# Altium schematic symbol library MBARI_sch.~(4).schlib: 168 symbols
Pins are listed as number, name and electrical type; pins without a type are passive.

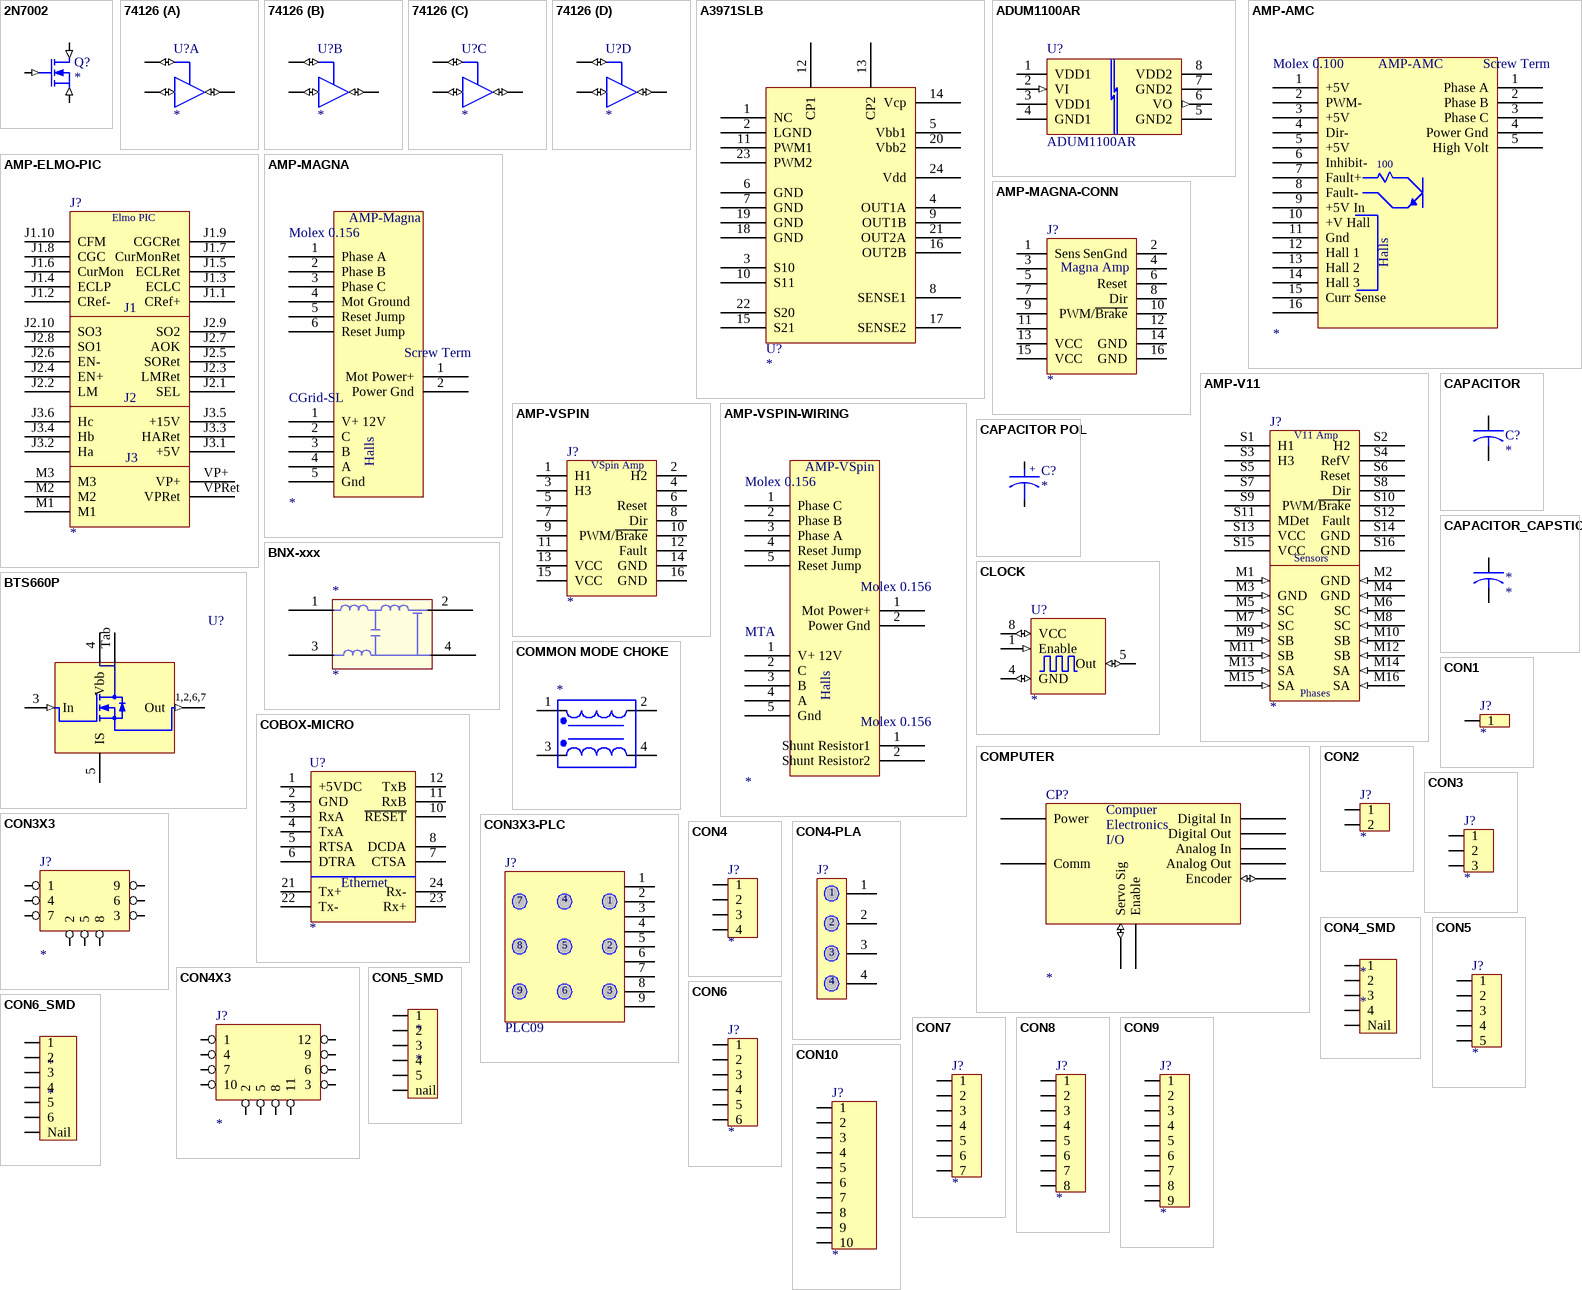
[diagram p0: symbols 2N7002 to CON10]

## 2N7002
designator Q?
N-Channel FET
footprint SOT-23
pins: 1 G (in), 2 S (in), 3 D (in)

## 74126
designator U?
Tri-State Quad Buffer
footprint DIP14
pins on every part: 7 GND (io) hidden to GND, 14 VCC (io) hidden to VCC
part A pins: 1 C1 (io), 2 A1 (io), 3 Y1 (io)
part B pins: 4 C2 (io), 5 A2 (io), 6 Y2 (io)
part C pins: 8 Y3 (io), 9 A3 (io), 10 C3 (io)
part D pins: 11 Y4 (io), 12 A4 (io), 13 C4 (io)

## A3971SLB
designator U?
Allegro Dual DMOS Full-Bridge Driver
footprint Allegro SOIC 24
pins: 1 NC, 2 LGND, 3 S10, 4 OUT1A, 5 Vbb1, 6 GND, 7 GND, 8 SENSE1, 9 OUT1B, 10 S11, 11 PWM1, 12 CP1, 13 CP2, 14 Vcp, 15 S21, 16 OUT2B, 17 SENSE2, 18 GND, 19 GND, 20 Vbb2, 21 OUT2A, 22 S20, 23 PWM2, 24 Vdd

## ADUM1100AR
designator U?
Digital Isolator; Manufacturer: Analog Devices; Vendor: Arrow Electronics
footprint SO-G8/D5
pins: 1 VDD1 (power), 2 VI (in), 3 VDD1 (power), 4 GND1 (power), 5 GND2 (power), 6 VO (out), 7 GND2 (power), 8 VDD2 (power)

## AMP-AMC
designator ?
pins: 1 Phase A (power), 1 +5V (power), 2 Phase B (power), 2 PWM- (power), 3 Phase C (power), 3 +5V (power), 4 Power Gnd (power), 4 Dir- (power), 5 High Volt (power), 5 +5V (power), 6 Inhibit- (power), 7 Fault+ (power), 8 Fault- (power), 9 +5V In (power), 10 +V Hall (power), 11 Gnd (power), 12 Hall 1 (power), 13 Hall 2 (power), 14 Hall 3 (power), 15 Curr Sense (power), 16 (power)

## AMP-ELMO-PIC
designator J?
Elmo Piccolo Amp
footprint ELMO-PIC
pins: J1.1 CRef+, J1.2 CRef-, J1.3 ECLC, J1.4 ECLP, J1.5 ECLRet, J1.6 CurMon, J1.7 CurMonRet, J1.8 CGC, J1.9 CGCRet, J1.10 CFM, J2.1 SEL, J2.2 LM, J2.3 LMRet, J2.4 EN+, J2.5 SORet, J2.6 EN-, J2.7 AOK, J2.8 SO1, J2.9 SO2, J2.10 SO3, J3.1 +5V, J3.2 Ha, J3.3 HARet, J3.4 Hb, J3.5 +15V, J3.6 Hc, M1, M2, M3, VP+, VPRet

## AMP-MAGNA
designator ?
pins: 1 Phase A (power), 1 V+ 12V (power), 1 Mot Power+ (power), 2 Phase B (power), 2 C (power), 2 Power Gnd (power), 3 Phase C (power), 3 B (power), 4 Mot Ground (power), 4 A (power), 5 Gnd (power), 5 Reset Jump (power), 6 Reset Jump (power)

## AMP-MAGNA-CONN
designator J?
Magma Amp board 2x8, 2mm connector
footprint HDR2X8_2MM
pins: 1 Sens (power), 2 SenGnd (power), 3 (power), 4 (power), 5 (power), 6 Reset (power), 7 (power), 8 Dir (power), 9 (power), 10 PWM/~{Brake} (power), 11 (power), 12 (power), 13 VCC (power), 14 GND (power), 15 VCC (power), 16 GND (power)

## AMP-V11
designator J?
Velocity11 Amp board 2 2x8, 2mm connectors
footprint V11-AMP
pins: M1 (in), M2 GND (in), M3 GND (in), M4 GND (in), M5 SC (in), M6 SC (in), M7 SC (in), M8 SC (in), M9 SB (in), M10 SB (in), M11 SB (in), M12 SB (in), M13 SA (in), M14 SA (in), M15 SA (in), M16 SA (in), S1 H1 (power), S2 H2 (power), S3 H3 (power), S4 RefV (power), S5 (power), S6 Reset (power), S7 (power), S8 Dir (power), S9 (power), S10 PWM/~{Brake} (power), S11 MDet (power), S12 Fault (power), S13 VCC (power), S14 GND (power), S15 VCC (power), S16 GND (power)

## AMP-VSPIN
designator J?
VSpin Amp board 2x8, 2mm connector
footprint VSPIN-AMP
pins: 1 H1 (power), 2 H2 (power), 3 H3 (power), 4 (power), 5 (power), 6 Reset (power), 7 (power), 8 Dir (power), 9 (power), 10 PWM/~{Brake} (power), 11 (power), 12 Fault (power), 13 VCC (power), 14 GND (power), 15 VCC (power), 16 GND (power)

## AMP-VSPIN-WIRING
designator ?
pins: 1 Phase C (power), 1 V+ 12V (power), 1 Mot Power+ (power), 1 Shunt Resistor1, 2 Phase B (power), 2 C (power), 2 Power Gnd (power), 2 Shunt Resistor2, 3 Phase A (power), 3 B (power), 4 A (power), 4 Reset Jump (power), 5 Gnd (power), 5 Reset Jump (power)

## BNX-xxx
designator *
pins: 1 B, 2 CB, 3 PSG, 4 CG

## BTS660P
designator U?
High Side High Current ProFET; ManufPartNo: BTS660P; Manufacturer: Infineon
footprint TO-220-7-3 (Footprint not found)
footprint TO-220-7SMD (Footprint not found)
pins: 1 Out (out), 2 Out (out), 3 In (in) "Ground to turn on", 4 Vbb (power), 5 IS "Current sense", 6 Out (out), 7 Out (out), Tab Vbb (power)

## CAPACITOR
designator C?
Capacitor
pins: 1, 2

## CAPACITOR POL
designator C?
Capacitor
pins: 1, 2

## CAPACITOR_CAPSTICK
designator *
pins: 1, 2

## CLOCK
designator U?
Clock Chip
footprint DIP8
pins: 1 Enable (in), 4 GND (io), 5 Out (io), 8 VCC (io)

## COBOX-MICRO
designator U?
CoBox Micro Terminal Server
footprint COBOX-MICRO
pins: 1 +5VDC, 2 GND, 3 RxA, 4 TxA, 5 RTSA, 6 DTRA, 7 CTSA, 8 DCDA, 10 ~{RESET}, 11 RxB, 12 TxB, 21 Tx+, 22 Tx-, 23 Rx+, 24 Rx-

## COMMON MODE CHOKE
designator *  (mechanical)
footprint Pulse_BigFoot (Pulse engineering big foot footprint)
pins: 1 (power), 2, 3, 4

## COMPUTER
designator CP?
computer
pins: 1 Power (power), 2 Digital In (power), 3 Digital Out (power), 4 Analog In (power), 5 Analog Out (power), 6 Comm (power), 7 Enable (power), 8 Servo Sig (io), 15 Encoder (io)

## CON1
designator J?
Connector
footprint SIP1
pins: 1

## CON2
designator J?
Connector
footprint SIP2
pins: 1, 2

## CON3
designator J?
Connector
footprint SIP3
pins: 1, 2, 3

## CON3X3
designator J?
9 pin connector
footprint PHOENIX1803497
footprint SIP9
footprint CGRID9
footprint MTA-9
pins: 1 (io), 2 (io), 3 (io), 4 (io), 5 (io), 6 (io), 7 (io), 8 (io), 9 (io)

## CON3X3-PLC
designator J?, comment PLC09
Positronic 9 pin connector
footprint PLC09 (Positronic 3x3 pins)
footprint PLC09-RA
pins: 1 (power), 2 (power), 3 (power), 4 (power), 5 (power), 6 (power), 7 (power), 8 (power), 9 (power)

## CON4
designator J?
Connector
footprint SIP4
footprint Microfit3-1x4 SMT RA Nail (Microfit 3 Single Row 4 Position SMT Right Angle Nail)
pins: 1, 2, 3, 4

## CON4-PLA
designator J?
Positronic 4 pin connector; ManufPartNo: PLA04
footprint PLA04 (Positronic 1x4 pin)
footprint PLA04-RA
pins: 1, 2, 3, 4

## CON4_SMD
designator *
footprint Microfit3-1x4 SMT RA Nail (Microfit 3 Single Row 4 Position SMT Right Angle Nail)
pins: 1, 2, 3, 4, nail Nail

## CON4X3
designator J?
12 pin connector
footprint PHOENIX1803523
footprint SIP12
footprint CGRID12
pins: 1 (io), 2 (io), 3 (io), 4 (io), 5 (io), 6 (io), 7 (io), 8 (io), 9 (io), 10 (io), 11 (io), 12 (io)

## CON5
designator J?
Connector
footprint SIP5
pins: 1, 2, 3, 4, 5

## CON5_SMD
designator *
Connector
footprint Microfit3-1x5 SMT RA Nail (Microfit 3.0 Single Row SMT with Nails 5 Position)
pins: 1, 2, 3, 4, 5, nail

## CON6
designator J?
Connector
footprint SIP6
pins: 1, 2, 3, 4, 5, 6

## CON6_SMD
designator *
footprint Microfit3-1x6 SMT RA Nail (Microfit 3 Single Row 6 Position SMT Right Angle Nail)
pins: 1, 2, 3, 4, 5, 6, Nail "mechanical"

## CON7
designator J?
Connector
footprint SIP7
pins: 1, 2, 3, 4, 5, 6, 7

## CON8
designator J?
Connector
footprint SIP8
pins: 1, 2, 3, 4, 5, 6, 7, 8

## CON9
designator J?
Connector
footprint SIP9
pins: 1, 2, 3, 4, 5, 6, 7, 8, 9

## CON10
designator J?
Connector
footprint SIP10
pins: 1, 2, 3, 4, 5, 6, 7, 8, 9, 10

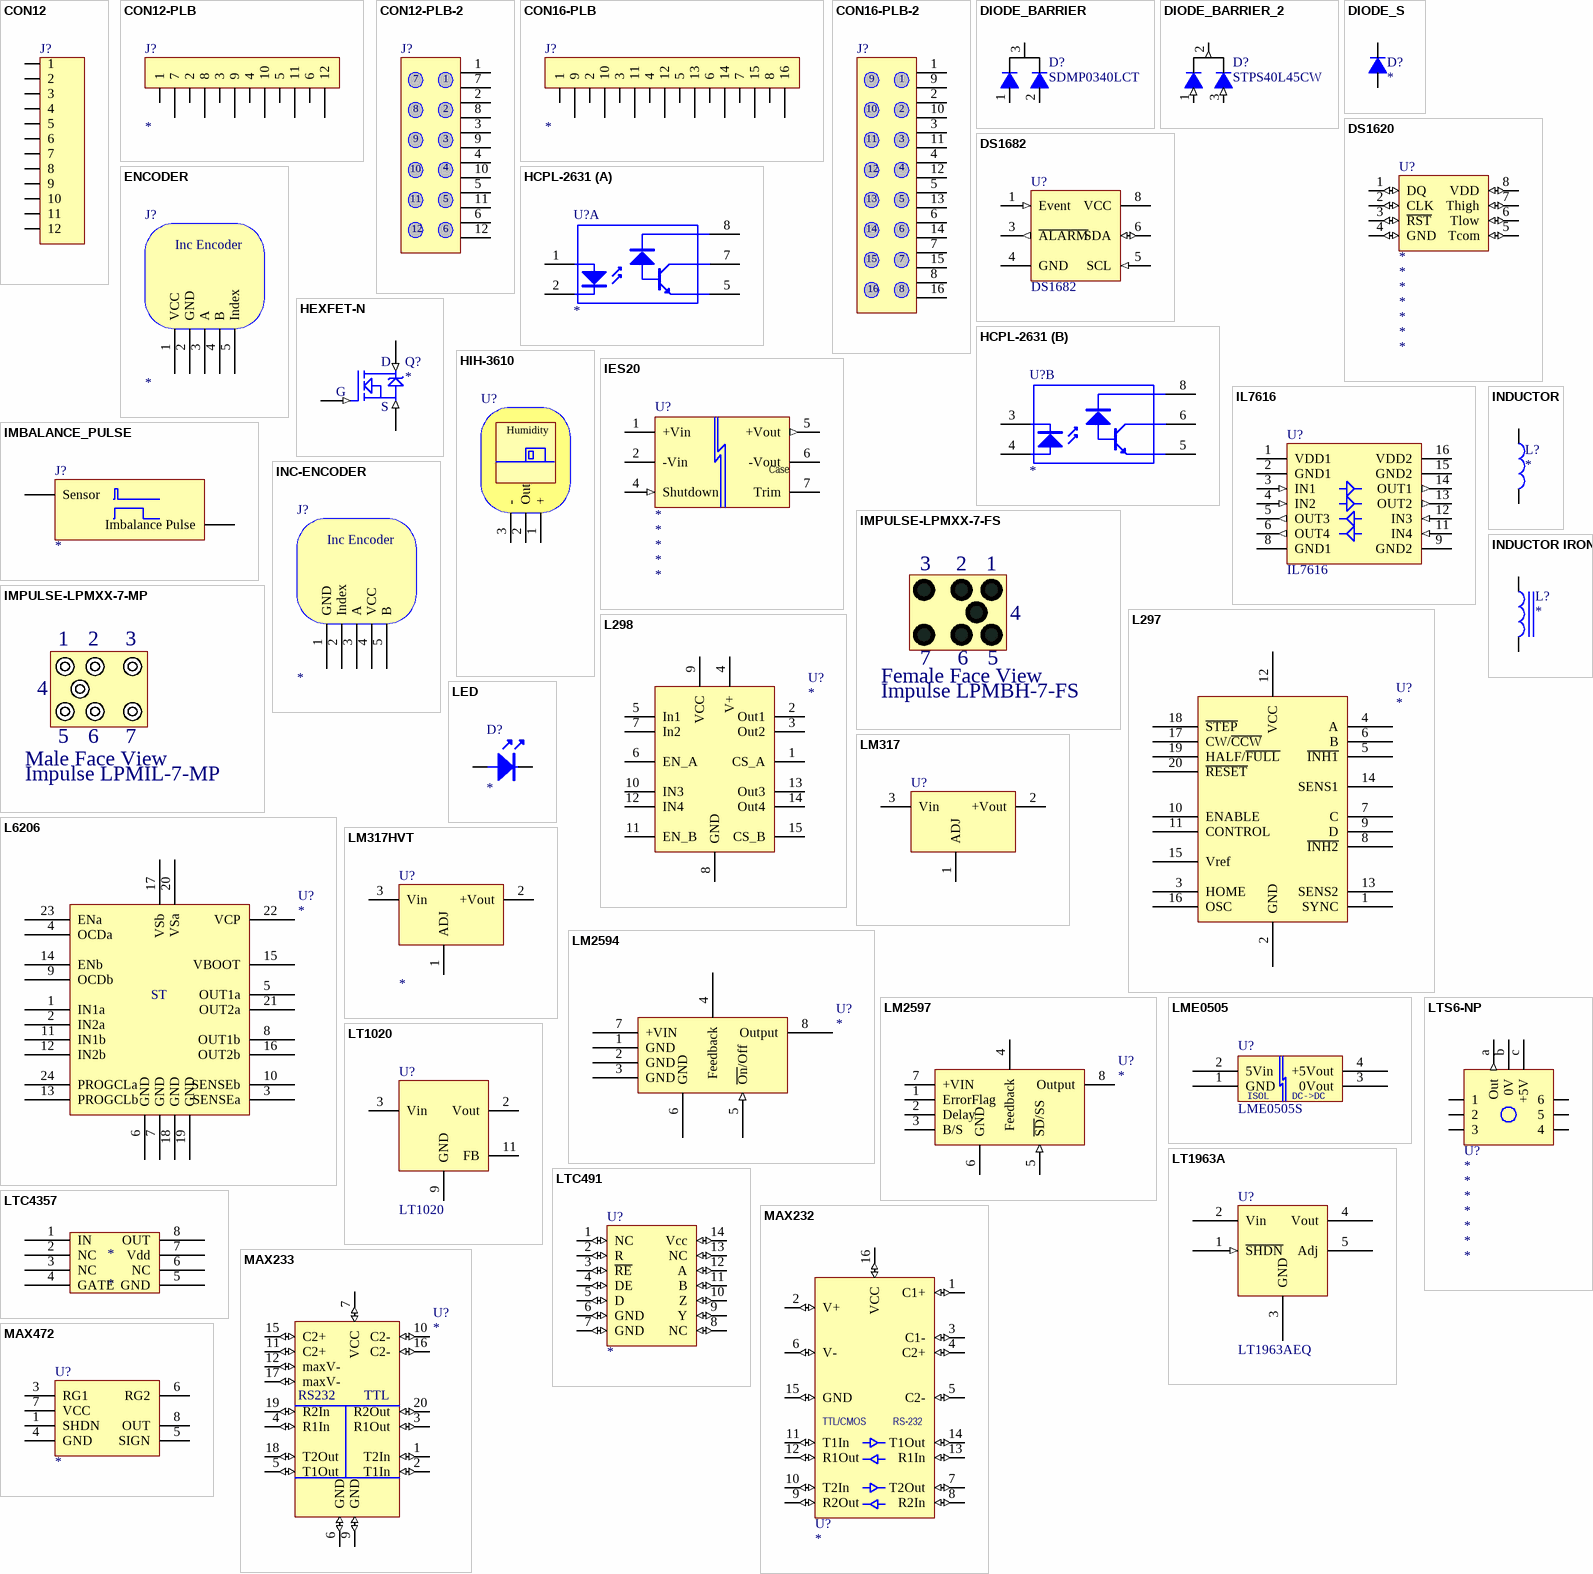
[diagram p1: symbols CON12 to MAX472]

## CON12
designator J?
Connector 12 pin
footprint SIP12 (Footprint not found)
pins: 1, 2, 3, 4, 5, 6, 7, 8, 9, 10, 11, 12

## CON12-PLB
designator J?
Positronic 12 pin connector
footprint PLB12
footprint PLB12-RA
pins: 1, 2, 3, 4, 5, 6, 7, 8, 9, 10, 11, 12

## CON12-PLB-2
designator J?
Positronic 12 pin connector; ManufPartNo: PLB12
footprint PLB12
footprint PLB12-RA
pins: 1, 2, 3, 4, 5, 6, 7, 8, 9, 10, 11, 12

## CON16-PLB
designator J?
Positronic 16 pin connector
footprint PLB16
footprint PLB16-RA
pins: 1, 2, 3, 4, 5, 6, 7, 8, 9, 10, 11, 12, 13, 14, 15, 16

## CON16-PLB-2
designator J?
Positronic 16 pin connector; ManufPartNo: PLB16
footprint PLB16 (Positronic 2x8 pins)
footprint PLB16-RA
pins: 1, 2, 3, 4, 5, 6, 7, 8, 9, 10, 11, 12, 13, 14, 15, 16

## DIODE_BARRIER
designator D?, comment SDMP0340LCT
Schottky Barrier Diode, Com Cathode; Manufacturer: Diodes Inc; VendorPartNo: SDMP0340LCTDICT-ND; Cost/ea: .065; Reference: T033, 581; Vendor: Digi-Key
footprint SOT-523 (Diodes Inc SOT-523)
pins: 1 A1 (io), 2 A2 (io), 3 K (io)

## DIODE_BARRIER_2
designator D?, comment STPS40L45CW
Schottky Barrier Diode, Com Cathode; Manufacturer: IRF
footprint TO-247AC (Footprint not found)
pins: 1 A1 (in), 2 K (out), 3 A2 (in)

## DIODE_S
designator D?
Diode
footprint DIODE0.4
pins: 1 K (io), 2 A (io)

## DS1620
designator U?
DallasSemi Digital Thermometer and Thermostat
footprint DIP-8
footprint SO-8
pins: 1 DQ (io), 2 CLK (io), 3 ~{RST} (io), 4 GND (io), 5 Tcom (io), 6 Tlow (io), 7 Thigh (io), 8 VDD (io)

## DS1682
designator U?
Dallas Semi Elapsed Time Recorder with Alarm
footprint SOIC-8
pins: 1 Event (in) "Active High", 3 ~{ALARM} (out), 4 GND (power), 5 SCL (in) "Serial Clock", 6 SDA (io) "Serial I/O", 8 VCC (power) "2.5 - 5.5 VDC"

## ENCODER
designator J?
encoder
pins: 1 VCC (power), 2 GND (power), 3 A (power), 4 B (power), 5 Index (power)

## HCPL-2631
designator U?
Optoisolator
footprint DIP8
pins on every part: 5 GND, 8 VCC (power)
part A pins: 1 A1, 2 K2, 7 Vo1
part B pins: 3 A2, 4 K2, 6 Vo2

## HEXFET-N
designator Q?
HexFET
footprint HEXFET-DIP4
pins: 1 G (in), 2 D (in), 3 S (in)

## HIH-3610
designator U?
Humidity Sensor
footprint SIP3
footprint SIP3_050
footprint HIH3610_100
footprint HIH3610_050
pins: 1 + (power), 2 Out (power), 3 - (power)

## IES20
designator U?
Power One IES 20W DC->DC Isolated Converter
footprint POWERONE-IES
pins: 1 +Vin (power), 2 -Vin (power), 4 Shutdown (in), 5 +Vout (out), 6 -Vout (power), 7 Trim

## IL7616
designator U?
NVE IsoLoop Digital Coupler; Cost/ea: 7.10; Vendor: Digi-Key
footprint SOIC16-0.15 (Footprint not found)
footprint SOIC16-0.3 (Footprint not found)
pins: 1 VDD1 (power), 2 GND1 (power), 3 IN1 (in), 4 IN2 (in), 5 OUT3 (out), 6 OUT4 (out), 8 GND1 (power), 9 GND2 (power), 11 IN4 (in), 12 IN3 (in), 13 OUT2 (out), 14 OUT1 (out), 15 GND2 (power), 16 VDD2 (power)

## IMBALANCE_PULSE
designator J?
safety circuit
pins: 2 Sensor (power), 3 Imbalance Pulse (power)

## IMPULSE-LPMXX-7-FS
designator J?  DescSheet: Impulse LPMBH-7-FS
Impulse LPMxx-7-FS Connector; DescSheet: Impulse LPMIL-7-FS

## IMPULSE-LPMXX-7-MP
designator J?  DescSheet: Impulse LPMIL-7-MP
Impulse LPMxx-7-MP Connector; DescSheet: Impulse LPMBH-7-MP

## INC-ENCODER
designator J?
encoder
pins: 1 GND (power), 2 Index (power), 3 A (power), 4 VCC (power), 5 B (power)

## INDUCTOR
designator L?
Inductor
pins: 1, 2

## INDUCTOR IRON
designator L?
Inductor
pins: 1, 2

## L297
designator U?
L297 Stepper Controller
footprint DIP20
pins: 1 SYNC, 2 GND, 3 HOME, 4 A, 5 ~{INH1}, 6 B, 7 C, 8 ~{INH2}, 9 D, 10 ENABLE, 11 CONTROL, 12 VCC, 13 SENS2, 14 SENS1, 15 Vref, 16 OSC, 17 CW/~{CCW}, 18 ~{STEP}, 19 HALF/~{FULL}, 20 ~{RESET}

## L298
designator U?
Dual Full Bridge Driver
footprint MULTIWATT15V
pins: 1 CS_A, 2 Out1, 3 Out2, 4 V+, 5 In1, 6 EN_A, 7 In2, 8 GND, 9 VCC, 10 IN3, 11 EN_B, 12 IN4, 13 Out3, 14 Out4, 15 CS_B

## L6206
designator U?
DMOS Dual Full Bridge Driver
footprint DIP24
footprint SO24
pins: 1 IN1a, 2 IN2a, 3 SENSEa, 4 OCDa, 5 OUT1a, 6 GND, 7 GND, 8 OUT1b, 9 OCDb, 10 SENSEb, 11 IN1b, 12 IN2b, 13 PROGCLb, 14 ENb, 15 VBOOT, 16 OUT2b, 17 VSb, 18 GND, 19 GND, 20 VSa, 21 OUT2a, 22 VCP, 23 ENa, 24 PROGCLa

## LED
designator D?
LED
footprint LED265
pins: 1 A, 2 K

## LM317
designator U?
Regulator
footprint TO-220; pin to pad 4>2
footprint SOT-223 (4 lead SMD NS:MP04A)
pins: 1 ADJ, 2 +Vout, 3 Vin, 4 +Vout

## LM317HVT
designator U?
Regulator
footprint TO-220
pins: 1 ADJ, 2 +Vout, 3 Vin

## LM2594
designator U?
Simple Switcher
footprint DIP8
pins: 1 GND, 2 GND, 3 GND, 4 Feedback, 5 ~{On}/Off (in), 6 GND (power), 7 +VIN (power), 8 Output (power)

## LM2597
designator U?
Simple Switcher 150kHz 0.5A
footprint DIP8
footprint SOIC-8
pins: 1 ErrorFlag, 2 Delay, 3 B/S, 4 Feedback, 5 ~{SD}/SS (in), 6 GND (power), 7 +VIN (power), 8 Output (power)

## LME0505
designator U?, comment LME0505S
DC->DC Isol Converter 5->5VDC; Manufacturer: C&D Technologies; VendorPartNo: 580-LME0505S; Cost/ea: 9.65; Reference: pg.741, 613; Vendor: Mouser
footprint LMEDCDC (Footprint not found)
footprint SIP4
pins: 1 GND, 2 5Vin, 3 0Vout, 4 +5Vout

## LT1020
designator U?
Micropower Regulator; Manufacturer: Linear Technology; Vendor: Digi-Key
footprint DIP14
footprint SOIC-16-0.3W (LTC SW pkg DWG# 05-08-1620); pin to pad 9>11 11>13
pins: 2 Vout (power), 3 Vin (power), 9 GND (power), 11 FB

## LT1963A
designator U?, comment LT1963AEQ
LDO Regulator, DD pkg; Manufacturer: Linear Technology; VendorPartNo: LT1963AEQ-ND; Cost/ea: 5.25; Vendor: Digi-Key
footprint DD-5 (Footprint not found)
pins: 1 ~{SHDN} (in) "~Shutdown", 2 Vin (power) "Input", 3 GND (power) "Ground", 4 Vout (power) "Output", 5 Adj "Adjust"

## LTC491
designator U?
LTC491 RS-232 <--> RS-485 converter
footprint DIP14
pins: 1 NC (io), 2 R (io), 3 ~{RE} (io), 4 DE (io), 5 D (io), 6 GND (io), 7 GND (io), 8 NC (io), 9 Y (io), 10 Z (io), 11 B (io), 12 A (io), 13 NC (io), 14 Vcc (io)

## LTC4357
designator *
pins: 1 IN, 2 NC, 3 NC, 4 GATE, 5 GND, 6 NC, 7 Vdd, 8 OUT

## LTS6-NP
designator U?
Current Transducer
footprint LTS6-NP
pins: 1, 2, 3, 4, 5, 6, a Out (out), b 0V (power), c +5V (power)

## MAX232
designator U?
MAX232 Communications Chip
footprint DIP16
pins: 1 C1+ (io), 2 V+ (io), 3 C1- (io), 4 C2+ (io), 5 C2- (io), 6 V- (io), 7 T2Out (io), 8 R2In (io), 9 R2Out (io), 10 T2In (io), 11 T1In (io), 12 R1Out (io), 13 R1In (io), 14 T1Out (io), 15 GND (io), 16 VCC (io)

## MAX233
designator U?
MAX233 Communications Chip
footprint DIP20
pins: 1 T2In (io), 2 T1In (io), 3 R1Out (io), 4 R1In (io), 5 T1Out (io), 6 GND (io), 7 VCC (io), 9 GND (io), 10 C2- (io), 11 C2+ (io), 12 maxV- (io), 15 C2+ (io), 16 C2- (io), 17 maxV- (io), 18 T2Out (io), 19 R2In (io), 20 R2Out (io)

## MAX472
designator U?
Maxim High-Side Current Monitor
footprint DIP8
footprint SO-G8/E2.5
pins: 1 SHDN, 3 RG1, 4 GND, 5 SIGN, 6 RG2, 7 VCC, 8 OUT

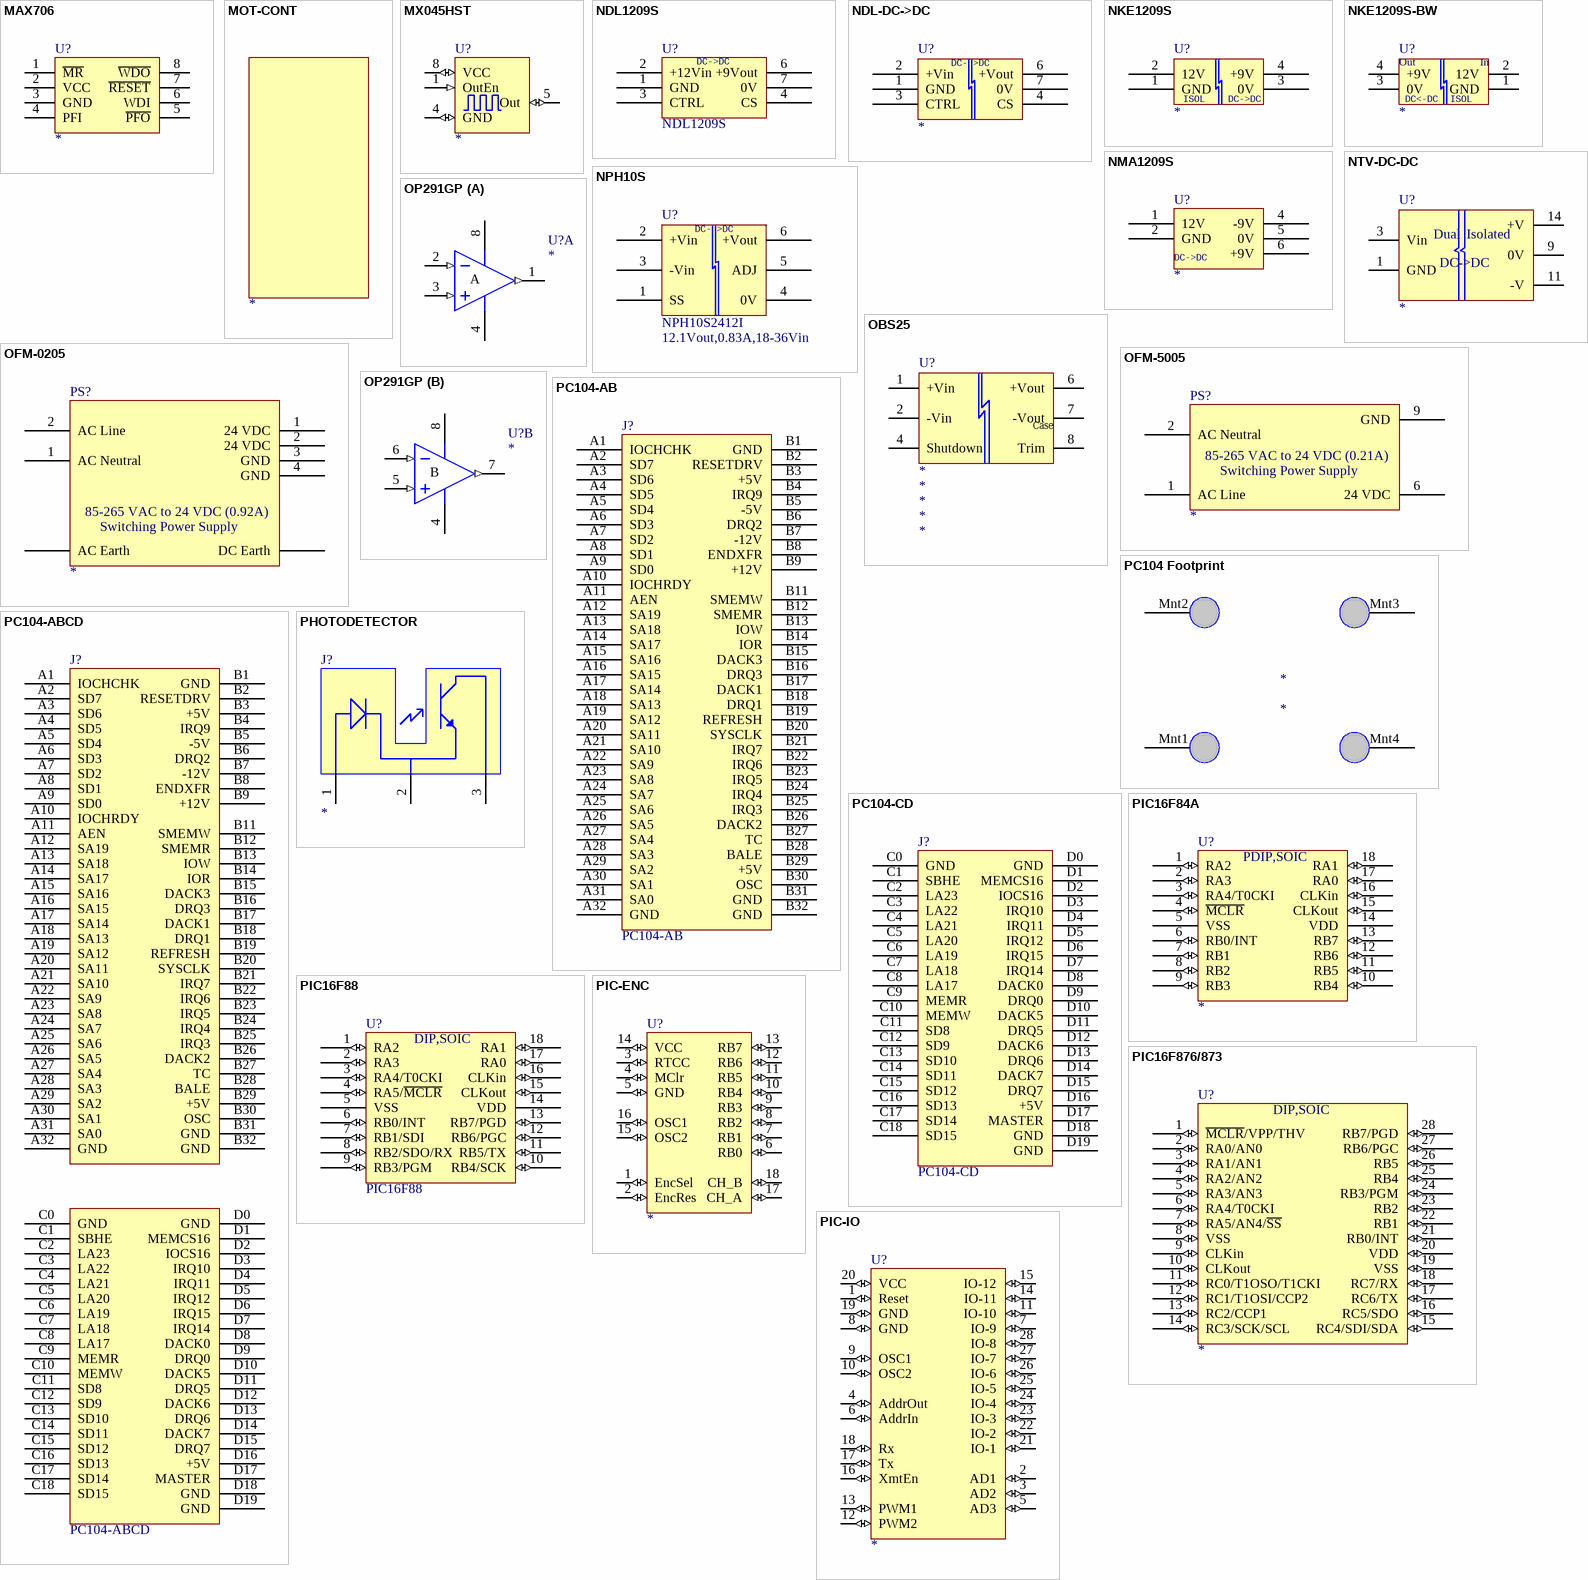
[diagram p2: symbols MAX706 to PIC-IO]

## MAX706
designator U?
Maxim uProc Supervisor
footprint DIP8
footprint SO-G8/E2.5
pins: 1 ~{MR}, 2 VCC, 3 GND, 4 PFI, 5 ~{PFO}, 6 WDI, 7 ~{RESET}, 8 ~{WDO}

## MOT-CONT
designator ?

## MX045HST
designator U?
Clock Chip
footprint DIP8
pins: 1 OutEn (in), 4 GND (io), 5 Out (io), 8 VCC (io)

## NDL1209S
designator U?
DC->DC Isol Converter 12->9VDC
footprint NDLDCDC
footprint SIP8
pins: 1 GND, 2 +12Vin, 3 CTRL, 4 CS, 6 +9Vout, 7 0V

## NDL-DC->DC
designator U?
DC->DC Isol Converter
footprint NDLDCDC
footprint SIP8
pins: 1 GND, 2 +Vin, 3 CTRL, 4 CS, 6 +Vout, 7 0V

## NKE1209S
designator U?
DC->DC Isol Converter 12->9VDC
footprint NKEDCDC
footprint SIP4
pins: 1 GND, 2 12V, 3 0V, 4 +9V

## NKE1209S-BW
designator U?
DC->DC Isol Converter 12->9VDC
footprint NKEDCDC
footprint SIP4
pins: 1 GND, 2 12V, 3 0V, 4 +9V

## NMA1209S
designator U?
DC->DC Isol Converter 12->9VDC
footprint NMADCDC
footprint SIP7
pins: 1 12V, 2 GND, 4 -9V, 5 0V, 6 +9V

## NPH10S
designator U?, comment NPH10S2412I  DescSheet: 12.1Vout,0.83A,18-36Vin
DC->DC Isol Converter 10W; Manufacturer: C&D Technologies; VendorPartNo: 580-NPH10S2412I; Cost/ea: 36.18; Reference: pg.1069; Vendor: Mouser
footprint NPH10S
pins: 1 SS, 2 +Vin, 3 -Vin, 4 0V, 5 ADJ, 6 +Vout

## NTV-DC-DC
designator U?
Dual Isol DC->DC Converter
footprint SO-NTV
pins: 1 GND, 3 Vin, 9 0V, 11 -V, 14 +V

## OBS25
designator U?
Power One OBS 25W DC->DC Isolated Converter
footprint POWERONE-OBS
pins: 1 +Vin, 2 -Vin, 4 Shutdown, 6 +Vout, 7 -Vout, 8 Trim

## OFM-0205
designator PS?
Astrodyne power supply 20 watts
footprint OFM020
pins: 1 AC Neutral, 1 24 VDC, 2 AC Line, 2 24 VDC, 3 GND, 4 GND, 10 AC Earth, 11 DC Earth

## OFM-5005
designator PS?
Astrodyne power supply 20 watts
footprint OFM020
pins: 1 AC Line, 2 AC Neutral, 6 24 VDC, 9 GND

## OP291GP
designator U?
Micropower Single-Supply Rail-to-Rail Input/Output Operational Amplifier
footprint DIP8
simulation model OP291G (SUBCKT)
pins on every part: 4 V- (power), 8 V+ (power)
part A pins: 1 OUT (out), 2 IN- (in), 3 IN+ (in)
part B pins: 5 IN+ (in), 6 IN- (in), 7 OUT (out)

## PC104 Footprint
designator *
pins: Mnt1, Mnt2, Mnt3, Mnt4

## PC104-AB
designator J?
PC/104 A&B rails
footprint PC104-AB (Footprint not found)
pins: A1 IOCHCHK, A2 SD7, A3 SD6, A4 SD5, A5 SD4, A6 SD3, A7 SD2, A8 SD1, A9 SD0, A10 IOCHRDY, A11 AEN, A12 SA19, A13 SA18, A14 SA17, A15 SA16, A16 SA15, A17 SA14, A18 SA13, A19 SA12, A20 SA11, A21 SA10, A22 SA9, A23 SA8, A24 SA7, A25 SA6, A26 SA5, A27 SA4, A28 SA3, A29 SA2, A30 SA1, A31 SA0, A32 GND, B1 GND, B2 RESETDRV, B3 +5V, B4 IRQ9, B5 -5V, B6 DRQ2, B7 -12V, B8 ENDXFR, B9 +12V, B10 KEY hidden, B11 SMEMW, B12 SMEMR, B13 IOW, B14 IOR, B15 DACK3, B16 DRQ3, B17 DACK1, B18 DRQ1, B19 REFRESH, B20 SYSCLK, B21 IRQ7, B22 IRQ6, B23 IRQ5, B24 IRQ4, B25 IRQ3, B26 DACK2, B27 TC, B28 BALE, B29 +5V, B30 OSC, B31 GND, B32 GND

## PC104-ABCD
designator J?
PC104 ABCD Rails
footprint PC104-ABCD (Footprint not found)
pins: A1 IOCHCHK, A2 SD7, A3 SD6, A4 SD5, A5 SD4, A6 SD3, A7 SD2, A8 SD1, A9 SD0, A10 IOCHRDY, A11 AEN, A12 SA19, A13 SA18, A14 SA17, A15 SA16, A16 SA15, A17 SA14, A18 SA13, A19 SA12, A20 SA11, A21 SA10, A22 SA9, A23 SA8, A24 SA7, A25 SA6, A26 SA5, A27 SA4, A28 SA3, A29 SA2, A30 SA1, A31 SA0, A32 GND, B1 GND, B2 RESETDRV, B3 +5V, B4 IRQ9, B5 -5V, B6 DRQ2, B7 -12V, B8 ENDXFR, B9 +12V, B11 SMEMW, B12 SMEMR, B13 IOW, B14 IOR, B15 DACK3, B16 DRQ3, B17 DACK1, B18 DRQ1, B19 REFRESH, B20 SYSCLK, B21 IRQ7, B22 IRQ6, B23 IRQ5, B24 IRQ4, B25 IRQ3, B26 DACK2, B27 TC, B28 BALE, B29 +5V, B30 OSC, B31 GND, B32 GND, C0 GND, C1 SBHE, C2 LA23, C3 LA22, C4 LA21, C5 LA20, C6 LA19, C7 LA18, C8 LA17, C9 MEMR, C10 MEMW, C11 SD8, C12 SD9, C13 SD10, C14 SD11, C15 SD12, C16 SD13, C17 SD14, C18 SD15, D0 GND, D1 MEMCS16, D2 IOCS16, D3 IRQ10, D4 IRQ11, D5 IRQ12, D6 IRQ15, D7 IRQ14, D8 DACK0, D9 DRQ0, D10 DACK5, D11 DRQ5, D12 DACK6, D13 DRQ6, D14 DACK7, D15 DRQ7, D16 +5V, D17 MASTER, D18 GND, D19 GND

## PC104-CD
designator J?
PC/104 C&D rails
footprint PC104-CD (Footprint not found)
pins: C0 GND, C1 SBHE, C2 LA23, C3 LA22, C4 LA21, C5 LA20, C6 LA19, C7 LA18, C8 LA17, C9 MEMR, C10 MEMW, C11 SD8, C12 SD9, C13 SD10, C14 SD11, C15 SD12, C16 SD13, C17 SD14, C18 SD15, C19 KEY hidden, D0 GND, D1 MEMCS16, D2 IOCS16, D3 IRQ10, D4 IRQ11, D5 IRQ12, D6 IRQ15, D7 IRQ14, D8 DACK0, D9 DRQ0, D10 DACK5, D11 DRQ5, D12 DACK6, D13 DRQ6, D14 DACK7, D15 DRQ7, D16 +5V, D17 MASTER, D18 GND, D19 GND

## PHOTODETECTOR
designator J?
slot sensor
pins: 1 A (power), 2 G (power), 3 C (power)

## PIC16F84A
designator U?
PIC16F84A microcontroller PDIP,SOIC package
footprint DIP18
pins: 1 RA2 (io), 2 RA3 (io), 3 RA4/T0CKI (io), 4 ~{MCLR} (io), 5 VSS (power), 6 RB0/INT (io), 7 RB1 (io), 8 RB2 (io), 9 RB3 (io), 10 RB4 (io), 11 RB5 (io), 12 RB6 (io), 13 RB7 (io), 14 VDD (power), 15 CLKout (io), 16 CLKin (io), 17 RA0 (io), 18 RA1 (io)

## PIC16F88
designator U?
PIC16F88 microcontroller DIP,SOIC package; Manufacturer: Microchip; Vendor: Digi-Key
footprint DIP18
pins: 1 RA2 (io), 2 RA3 (io), 3 RA4/T0CKI (io), 4 RA5/~{MCLR} (io), 5 VSS (power), 6 RB0/INT (io), 7 RB1/SDI (io), 8 RB2/SDO/RX (io), 9 RB3/PGM (io), 10 RB4/SCK (io), 11 RB5/TX (io), 12 RB6/PGC (io), 13 RB7/PGD (io), 14 VDD (power), 15 CLKout (io), 16 CLKin (io), 17 RA0 (io), 18 RA1 (io)

## PIC16F876/873
designator U?
PIC16F876/873 microcontroller DIP,SOIC package
footprint DIP28
footprint SOIC28
pins: 1 ~{MCLR}/VPP/THV (io), 2 RA0/AN0 (io), 3 RA1/AN1 (io), 4 RA2/AN2 (io), 5 RA3/AN3 (io), 6 RA4/T0CKI (io), 7 RA5/AN4/~{SS} (io), 8 VSS (io), 9 CLKin (io), 10 CLKout (io), 11 RC0/T1OSO/T1CKI (io), 12 RC1/T1OSI/CCP2 (io), 13 RC2/CCP1 (io), 14 RC3/SCK/SCL (io), 15 RC4/SDI/SDA (io), 16 RC5/SDO (io), 17 RC6/TX (io), 18 RC7/RX (io), 19 VSS (io), 20 VDD (io), 21 RB0/INT (io), 22 RB1 (io), 23 RB2 (io), 24 RB3/PGM (io), 25 RB4 (io), 26 RB5 (io), 27 RB6/PGC (io), 28 RB7/PGD (io)

## PIC-ENC
designator U?
Pic-Encoder J R Kerr
footprint DIP16
footprint SOIC16
pins: 1 EncSel (io), 2 EncRes (io), 3 RTCC (io), 4 MClr (io), 5 GND (io), 6 RB0 (io), 7 RB1 (io), 8 RB2 (io), 9 RB3 (io), 10 RB4 (io), 11 RB5 (io), 12 RB6 (io), 13 RB7 (io), 14 VCC (io), 15 OSC2 (io), 16 OSC1 (io), 17 CH_A (io), 18 CH_B (io)

## PIC-IO
designator U?
PIC-IO multifunction I/O controller
footprint DIP28_.3
pins: 1 Reset (io), 2 AD1 (io), 3 AD2 (io), 4 AddrOut (io), 5 AD3 (io), 6 AddrIn (io), 7 IO-9 (io), 8 GND (io), 9 OSC1 (io), 10 OSC2 (io), 11 IO-10 (io), 12 PWM2 (io), 13 PWM1 (io), 14 IO-11 (io), 15 IO-12 (io), 16 XmtEn (io), 17 Tx (io), 18 Rx (io), 19 GND (io), 20 VCC (io), 21 IO-1 (io), 22 IO-2 (io), 23 IO-3 (io), 24 IO-4 (io), 25 IO-5 (io), 26 IO-6 (io), 27 IO-7 (io), 28 IO-8 (io)

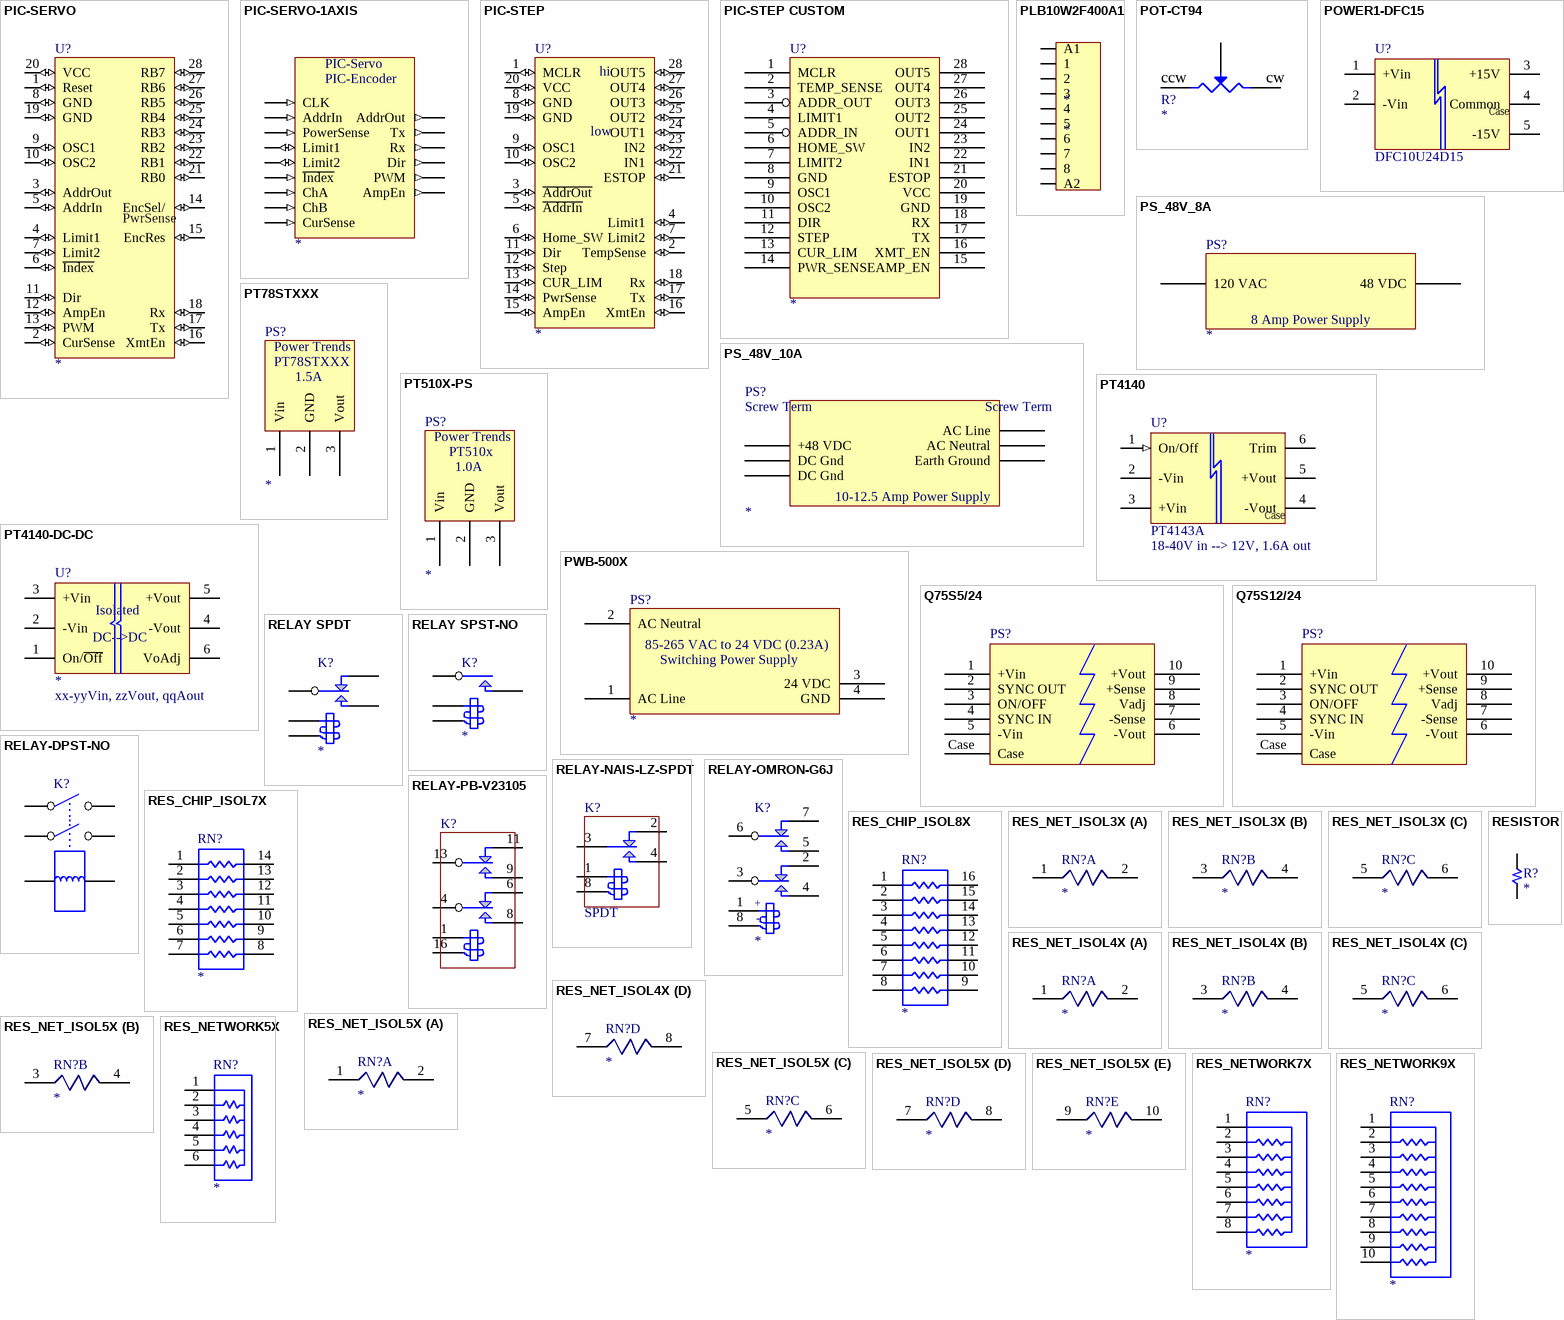
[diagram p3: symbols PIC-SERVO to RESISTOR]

## PIC-SERVO
designator U?
Pic-Servo Controller J R Kerr
footprint DIP28_.3
footprint SOIC28
pins: 1 Reset (io), 2 CurSense (io), 3 AddrOut (io), 4 Limit1 (io), 5 AddrIn (io), 6 ~{Index} (io), 7 Limit2 (io), 8 GND (io), 9 OSC1 (io), 10 OSC2 (io), 11 Dir (io), 12 AmpEn (io), 13 PWM (io), 14 EncSel/ (io), 15 EncRes (io), 16 XmtEn (io), 17 Tx (io), 18 Rx (io), 19 GND (io), 20 VCC (io), 21 RB0 (io), 22 RB1 (io), 23 RB2 (io), 24 RB3 (io), 25 RB4 (io), 26 RB5 (io), 27 RB6 (io), 28 RB7 (io)

## PIC-SERVO-1AXIS
designator ?
PIC-Servo Block with PIC-Encoder
pins: 1 CLK (in), 2 AddrIn (in), 3 PowerSense (in), 4 Limit1 (io), 5 Limit2 (io), 6 ~{Index} (in), 7 ChA (in), 8 ChB (in), 9 CurSense (in), 10 AddrOut (out), 11 Tx (out), 12 Rx (out), 13 Dir (out), 14 PWM (out), 15 AmpEn (out)

## PIC-STEP
designator U?
Pic-Step Controller J R Kerr
footprint DIP28_.3
footprint SOIC28
pins: 1 MCLR (io), 2 TempSense (io), 3 ~{AddrOut} (io), 4 Limit1 (io), 5 ~{Ad}~{drIn} (io), 6 Home_SW (io), 7 Limit2 (io), 8 GND (io), 9 OSC1 (io), 10 OSC2 (io), 11 Dir (io), 12 Step (io), 13 CUR_LIM (io), 14 PwrSense (io), 15 AmpEn (io), 16 XmtEn (io), 17 Tx (io), 18 Rx (io), 19 GND (io), 20 VCC (io), 21 ESTOP (io), 22 IN1 (io), 23 IN2 (io), 24 OUT1 (io), 25 OUT2 (io), 26 OUT3 (io), 27 OUT4 (io), 28 OUT5 (io)

## PIC-STEP CUSTOM
designator U?
Pic-Step Controller J R Kerr
footprint DIP28_.3
pins: 1 MCLR, 2 TEMP_SENSE, 3 ADDR_OUT, 4 LIMIT1, 5 ADDR_IN, 6 HOME_SW, 7 LIMIT2, 8 GND, 9 OSC1, 10 OSC2, 11 DIR, 12 STEP, 13 CUR_LIM, 14 PWR_SENSE, 15 AMP_EN, 16 XMT_EN, 17 TX, 18 RX, 19 GND, 20 VCC, 21 ESTOP, 22 IN1, 23 IN2, 24 OUT1, 25 OUT2, 26 OUT3, 27 OUT4, 28 OUT5

## PLB10W2F400A1
designator *
pins: 1, 2, 3, 4, 5, 6, 7, 8, A1, A2

## POT-CT94
designator R?
Potentiometer
footprint CT94
pins: 1 CCW, 2 W, 3 CW

## POWER1-DFC15
designator U?, comment DFC10U24D15
Power One DFC 22W DC->DC Isolated Converter +/-15V; VendorPartNo: 179-1023-ND; Manufacturer: Power-One; Cost/ea: 71.40; Reference: 1005; Vendor: Digi-Key
footprint POWERONE-DFC (Footprint not found)
pins: 1 +Vin, 2 -Vin, 3 +15V, 4 Common, 5 -15V

## PS_48V_8A
designator PS?
Power Supply
pins: 1 120 VAC (power), 3 48 VDC (power)

## PS_48V_10A
designator PS?
Power Supply
pins: 1 AC Line (power), 1 +48 VDC (power), 2 AC Neutral (power), 2 DC Gnd (power), 3 Earth Ground (power), 3 DC Gnd (power)

## PT78STXXX
designator PS?
Power Trends Switching Reg
footprint PT78ST-HORIZ
footprint PT78ST-VERT
pins: 1 Vin (power), 2 GND (power), 3 Vout (power)

## PT510X-PS
designator PS?
Power Trends Switching Reg
footprint PT510X-HORZ
footprint PT510X-VERT
pins: 1 Vin (power), 2 GND (power), 3 Vout (power)

## PT4140
designator U?, comment PT4143A  DescSheet: 18-40V in --> 12V, 1.6A out
Power Trends 20W DC->DC Isolated Converter; Manufacturer: TI Power Trends; Vendor: Digi-Key
footprint PT4140A (Footprint not found)
pins: 1 On/Off (in), 2 -Vin (power), 3 +Vin (power), 4 -Vout (power), 5 +Vout (power), 6 Trim

## PT4140-DC-DC
designator U?  DescSheet: xx-yyVin, zzVout, qqAout
TI Isol DC->DC Converter; Manufacturer: TI Powertrends; Vendor: Digi-Key
footprint TI-EGD (Footprint not found)
pins: 1 On/~{Off}, 2 -Vin (power), 3 +Vin (power), 4 -Vout (power), 5 +Vout (power), 6 VoAdj

## PWB-500X
designator PS?
Astrodyne power supply 5W watts PWB series
footprint PWB-500X
pins: 1 AC Line, 2 AC Neutral, 3 24 VDC, 4 GND

## Q75S5/24
designator PS?
BetaDyne Q75 Series Converter 5V Out 18-36V in
footprint Q75 Quarter Brick (BetaDYne Q75 Quarter Brick w/ Cu Case)
pins: 1 +Vin, 2 SYNC OUT, 3 ON/OFF, 4 SYNC IN, 5 -Vin, 6 -Vout, 7 -Sense, 8 Vadj, 9 +Sense, 10 +Vout, Case

## Q75S12/24
designator PS?
BetaDyne Q75 Series Converter
footprint Q75 Quarter Brick (BetaDYne Q75 Quarter Brick w/ Cu Case)
pins: 1 +Vin, 2 SYNC OUT, 3 ON/OFF, 4 SYNC IN, 5 -Vin, 6 -Vout, 7 -Sense, 8 Vadj, 9 +Sense, 10 +Vout, Case

## RELAY SPDT
designator K?
Relay SPDT
pins: 1 COIL1, 2 COIL2, 3 COMMON, 4 NO, 5 NC

## RELAY SPST-NO
designator K?
Relay SPST-NO
pins: 1 COIL1, 2 COIL2, 3 COMMON, 4 NO

## RELAY-DPST-NO
designator K?
Relay DPST-NO
pins: 1, 2, 3, 4, 5, 6

## RELAY-NAIS-LZ-SPDT
designator K?, comment SPDT
Nais LZ Relay SPDT; ManufPartNo: ALZ12F24; VendorPartNo: 255-1447-ND; Cost/ea: 2.16; Reference: T033, 942; Vendor: Digi-Key
footprint NAIS-LZ (Footprint not found)
pins: 1 COIL+, 2 NC, 3 COMMON, 4 NO, 5 NO hidden, 6 COMMON hidden, 7 NC hidden, 8 COIL-

## RELAY-OMRON-G6J
designator K?
Omron G6J Relay DPDT
footprint OMRON-G6J
pins: 1 COIL+, 2 NC1, 3 COMMON1, 4 NO1, 5 NO2, 6 COMMON2, 7 NC2, 8 COIL-

## RELAY-PB-V23105
designator K?
P&B V23105 Relay DPDT; ManufPartNo: V23105A5...; VendorPartNo: PB38x-ND; Reference: T033, 946; Vendor: Digi-Key
footprint DIP16
pins: 1 COIL, 4 COMMON1, 6 NC1, 8 NO1, 9 NO2, 11 NC2, 13 COMMON2, 16 COIL

## RES_CHIP_ISOL7X
designator RN?
Resistor Chip Isolated 7x
footprint DIP14
pins: 1, 2, 3, 4, 5, 6, 7, 8, 9, 10, 11, 12, 13, 14

## RES_CHIP_ISOL8X
designator RN?
Resistor Chip Isolated 8x
footprint DIP16
pins: 1, 2, 3, 4, 5, 6, 7, 8, 9, 10, 11, 12, 13, 14, 15, 16

## RES_NET_ISOL3X
designator RN?
Resistor Network Isolated 3x
footprint SIP6
part A pins: 1, 2
part B pins: 3, 4
part C pins: 5, 6

## RES_NET_ISOL4X
designator RN?
Resistor Network Isolated 4x
footprint SIP8
part A pins: 1, 2
part B pins: 3, 4
part C pins: 5, 6
part D pins: 7, 8

## RES_NET_ISOL5X
designator RN?
Resistor Network Isolated 5x
footprint SIP10
part A pins: 1, 2
part B pins: 3, 4
part C pins: 5, 6
part D pins: 7, 8
part E pins: 9, 10

## RES_NETWORK5X
designator RN?
Resistor Network, 5x
footprint SIP6
pins: 1, 2, 3, 4, 5, 6

## RES_NETWORK7X
designator RN?
Resistor Network, 7x
footprint SIP8
pins: 1, 2, 3, 4, 5, 6, 7, 8

## RES_NETWORK9X
designator RN?
Resistor Network 9x
footprint SIP10
pins: 1, 2, 3, 4, 5, 6, 7, 8, 9, 10

## RESISTOR
designator R?
Resistor
footprint AXIAL0.7
footprint AXIAL0.6
footprint AXIAL0.8
pins: 1, 2

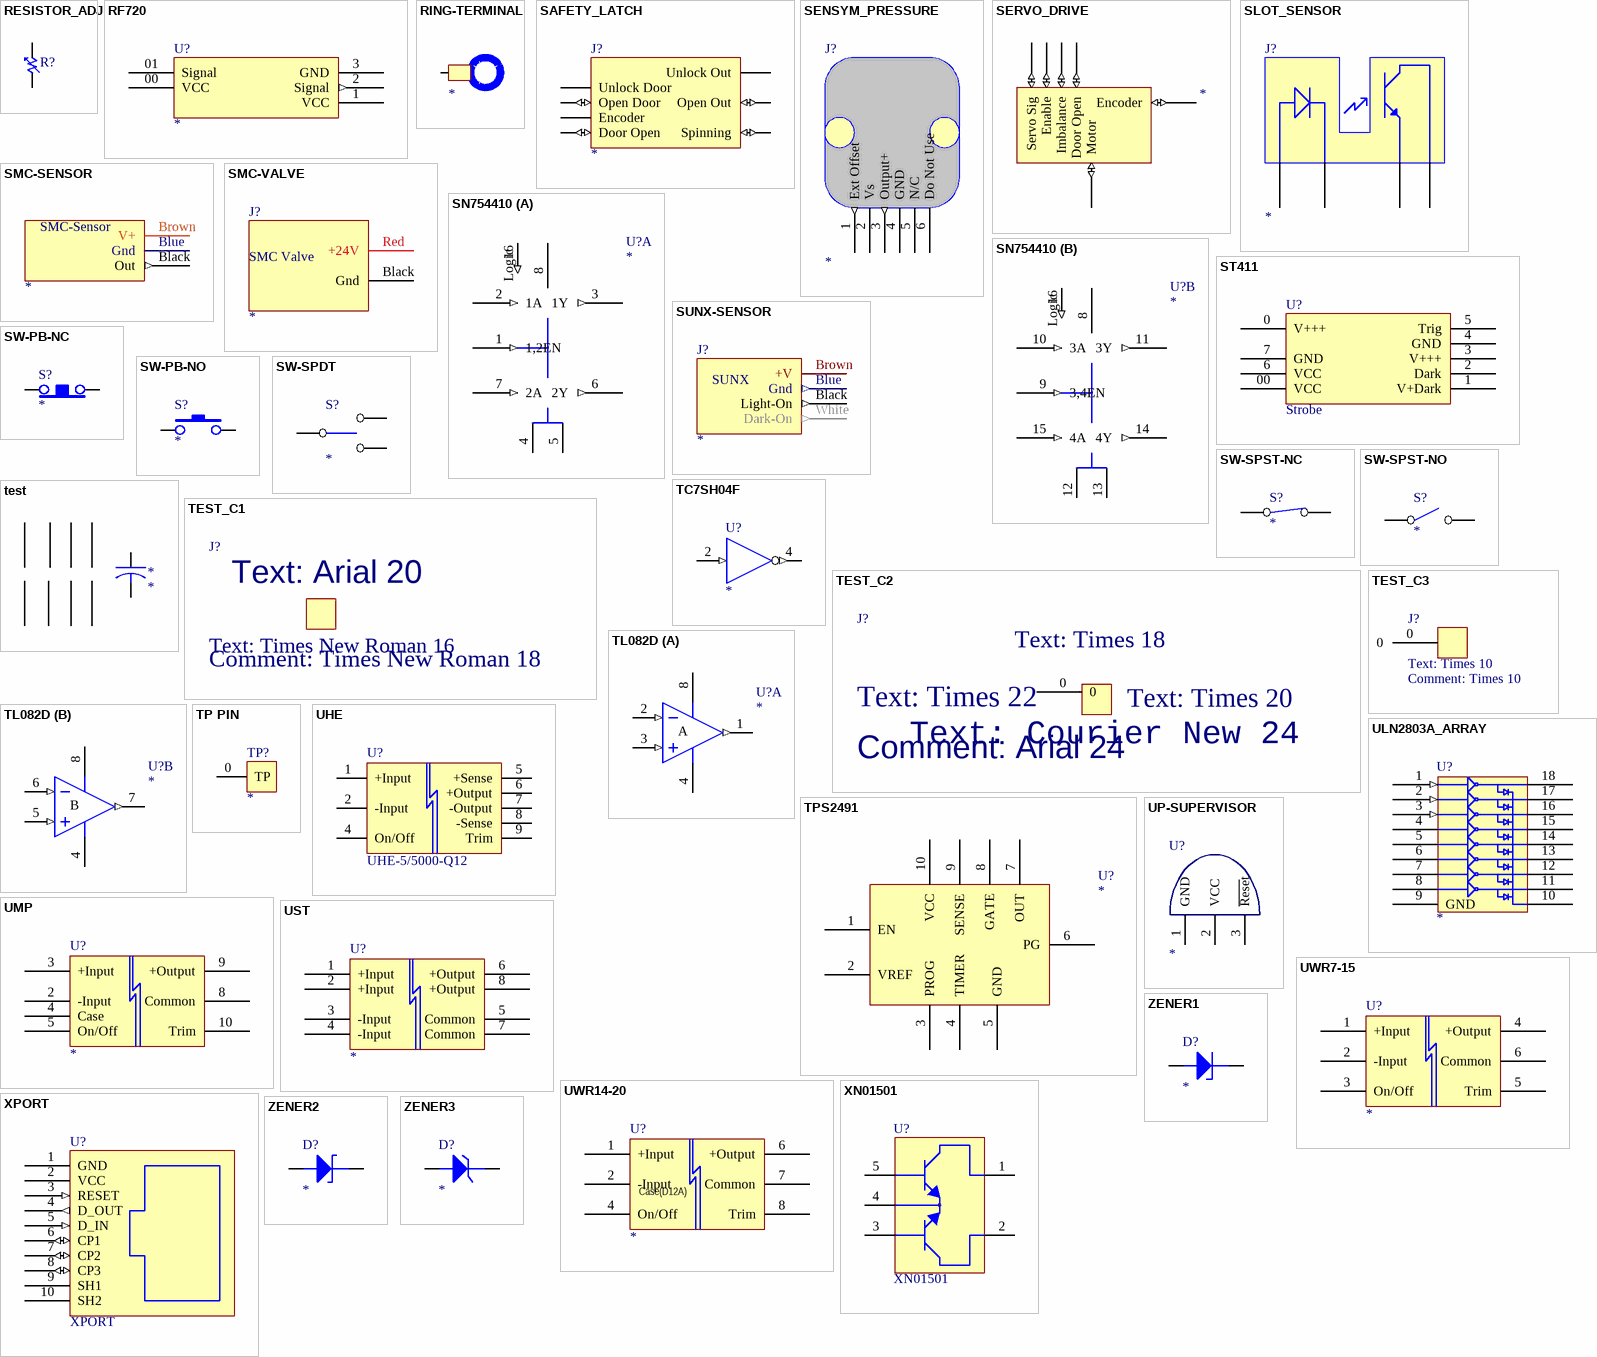
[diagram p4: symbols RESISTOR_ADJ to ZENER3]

## RESISTOR_ADJ
designator R?
Resistor Adjustable
footprint AXIAL0.7
footprint AXIAL0.6
footprint AXIAL0.8
pins: 1, 2

## RF720
designator U?
Novatech RF Beacon
footprint RF720
pins: 00 VCC (power), 1 VCC (power), 01 Signal (power), 2 Signal (out), 3 GND (power)

## RING-TERMINAL
designator ?
pins: 0

## SAFETY_LATCH
designator J?
safety circuit
pins: 1 Unlock Door (power), 2 Encoder (power), 3 Unlock Out (power), 4 Open Door (io), 5 Open Out (io), 6 Spinning (io), 7 Door Open (io)

## SENSYM_PRESSURE
designator J?
Sensym pressure sensor
footprint ASCX
pins: 1 Ext Offset (out), 2 Vs (power), 3 Output+ (out), 4 GND (power), 5 N/C, 6 Do Not Use

## SERVO_DRIVE
designator ?
pins: 9 Servo Sig (io), 10 Enable (io), 11 Motor (io), 12 Encoder (io), 13 Imbalance (io), 14 Door Open (io)

## SLOT_SENSOR
designator J?
slot sensor
pins: 1 A (power), 2 K (power), 3 C (power), 4 E (power)

## SMC-SENSOR
designator ?
pins: Black Out (out), Blue Gnd (power), Brown V+ (power)

## SMC-VALVE
designator J?
SMC Valve
pins: Black Gnd (power), Red +24V (power)

## SN754410
designator U?
Quad Half-H Driver
footprint DIP16
pins on every part: 8 VCC2 (power), 16 VCC1 (in)
part A pins: 1 1,2EN (in), 2 1A (in), 3 1Y (out), 4 GND (power), 5 GND (power), 6 2Y (out), 7 2A (in)
part B pins: 9 3,4EN (in), 10 3A (in), 11 3Y (out), 12 GND (power), 13 GND (power), 14 4Y (out), 15 4A (in)

## ST411
designator U?, comment Strobe
Novatech Strobe Beacon
footprint ST411 (Footprint not found)
pins: 00 VCC (power), 0 V+++ (power), 1 V+Dark (power), 2 Dark (power), 3 V+++ (power), 4 GND (power), 5 Trig (power), 6 VCC (power), 7 GND (power)

## SUNX-SENSOR
designator J?
SUNX slot sensor
pins: Black Light-On (out), Blue Gnd (out), Brown +V (power), White Dark-On (out)

## SW-PB-NC
designator S?
pins: 1, 2

## SW-PB-NO
designator S?
pins: 1, 2

## SW-SPDT
designator S?
pins: 1, 2, 3

## SW-SPST-NC
designator S?
pins: 1 COMMON, 2 NO

## SW-SPST-NO
designator S?
pins: 1, 2

## TC7SH04F
designator U?
Single CMOS Inverter SMD
footprint SMV-5
pins: 2 A (in), 3 GND (in) hidden to GND, 4 Y (out), 5 VCC (in) hidden to VCC

## test
designator *
pins: 1, 1, 1, 1, 1, 2, 2, 2, 2, 2

## TEST_C1
designator J?, comment Comment: Times New Roman 18

## TEST_C2
designator J?, comment Comment: Arial 24
pins: 0

## TEST_C3
designator J?, comment Comment: Times 10
pins: 0

## TL082D
designator U?
JFET-Input Operational Amplifier
footprint SO-G8/E2.5
simulation model TL082 (SUBCKT)
pins on every part: 4 V- (power), 8 V+ (power)
part A pins: 1 OUT (out), 2 IN- (in), 3 IN+ (in)
part B pins: 5 IN+ (in), 6 IN- (in), 7 OUT (out)

## TP PIN
designator TP?
Pad Pin for testpoints
footprint TP-PAD
pins: 0 TP (power)

## TPS2491
designator U?
Retry Positive High-Voltage Power-Limiting Hot Swap Controller
pins: 1 EN, 2 VREF, 3 PROG, 4 TIMER, 5 GND, 6 PG, 7 OUT, 8 GATE, 9 SENSE, 10 VCC

## UHE
designator U?, comment UHE-5/5000-Q12
Datel UHE DC->DC Isolated Converter
footprint DATEL-UHE (Datel UHE 1.6x2.0 DC/DC Converter)
pins: 1 +Input, 2 -Input, 4 On/Off, 5 +Sense, 6 +Output, 7 -Output, 8 -Sense, 9 Trim

## ULN2803A_ARRAY
designator U?
Darlington Transistor Array
footprint DIP18
pins: 1 IN (in), 2 IN (in), 3 IN (in), 4 In, 5 In, 6 In, 7 In, 8 In, 9 GND, 10 COM, 11 Out, 12 Out, 13 Out, 14 Out, 15 Out, 16 Out, 17 Out, 18 Out

## UMP
designator U?
Datel UMP DC->DC Isolated Converter
footprint DATEL_UMP
pins: 2 -Input, 3 +Input, 4 Case, 5 On/Off, 8 Common, 9 +Output, 10 Trim

## UP-SUPERVISOR
designator U?
MicroProcessor Supervisor
footprint TO92C
pins: 1 GND (power), 2 VCC (power), 3 ~{Rese}t (power)

## UST
designator U?
Datel UST DC->DC Isolated Converter
footprint DATEL_UST
pins: 1 +Input, 2 +Input, 3 -Input, 4 -Input, 5 Common, 6 +Output, 7 Common, 8 +Output

## UWR7-15
designator U?
Datel UWR DC->DC Isolated Converter
footprint DATEL_UWR
pins: 1 +Input, 2 -Input, 3 On/Off, 4 +Output, 5 Trim, 6 Common

## UWR14-20
designator U?
Datel UWR DC->DC Isolated Converter
footprint DATEL_UWR
pins: 1 +Input, 2 -Input, 4 On/Off, 6 +Output, 7 Common, 8 Trim

## XN01501
designator U?
Dual NPN Common Emitter Transistor
footprint SC-74A (Mini5 - G1 Panasonic)
pins: 1 C1 "TR1-Collector", 2 C2 "TR2-Collector", 3 B2 "TR2-Base", 4 Emitter "Common Emitter", 5 B1 "TR1-Base"

## XPORT
designator U?
Serial to Ethernet Converter
footprint XPORT
pins: 1 GND (power), 2 VCC (power), 3 RESET (in), 4 D_OUT (out), 5 D_IN (in), 6 CP1 (io), 7 CP2 (io), 8 CP3 (io), 9 SH1, 10 SH2

## ZENER1
designator D?
Zener Diode
footprint AXIAL0.7
footprint AXIAL0.8
footprint AXIAL0.9
footprint AXIAL0.3
pins: 1 A, 2 K

## ZENER2
designator D?
Zener Diode
footprint AXIAL0.7
footprint AXIAL0.8
footprint AXIAL0.9
footprint AXIAL0.3
pins: 1 A, 2 K

## ZENER3
designator D?
Zener Diode
footprint AXIAL0.7
footprint AXIAL0.8
footprint AXIAL0.9
footprint AXIAL0.3
pins: 1 A, 2 K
